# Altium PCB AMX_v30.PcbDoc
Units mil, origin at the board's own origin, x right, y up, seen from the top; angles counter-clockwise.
Board outline 2747.05 x 1800.98 mil, 4 copper layers (Top Layer, Internal Plane 1, Internal Plane 2, Bottom Layer), stack 30.634 mil thick; 78 components, 60 nets, 302 pads, 54 vias.
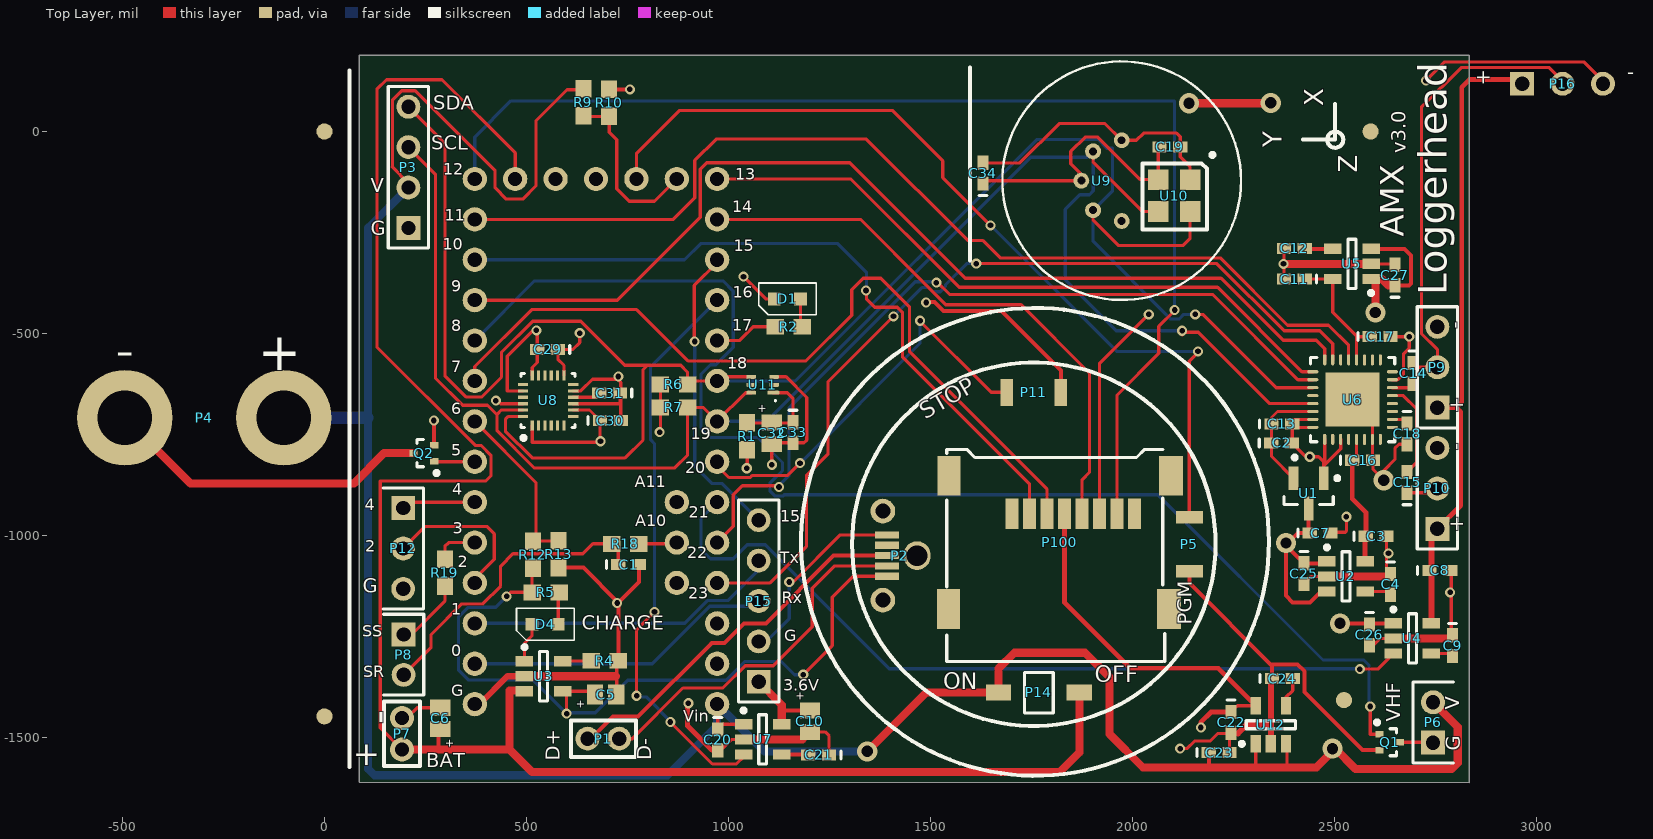
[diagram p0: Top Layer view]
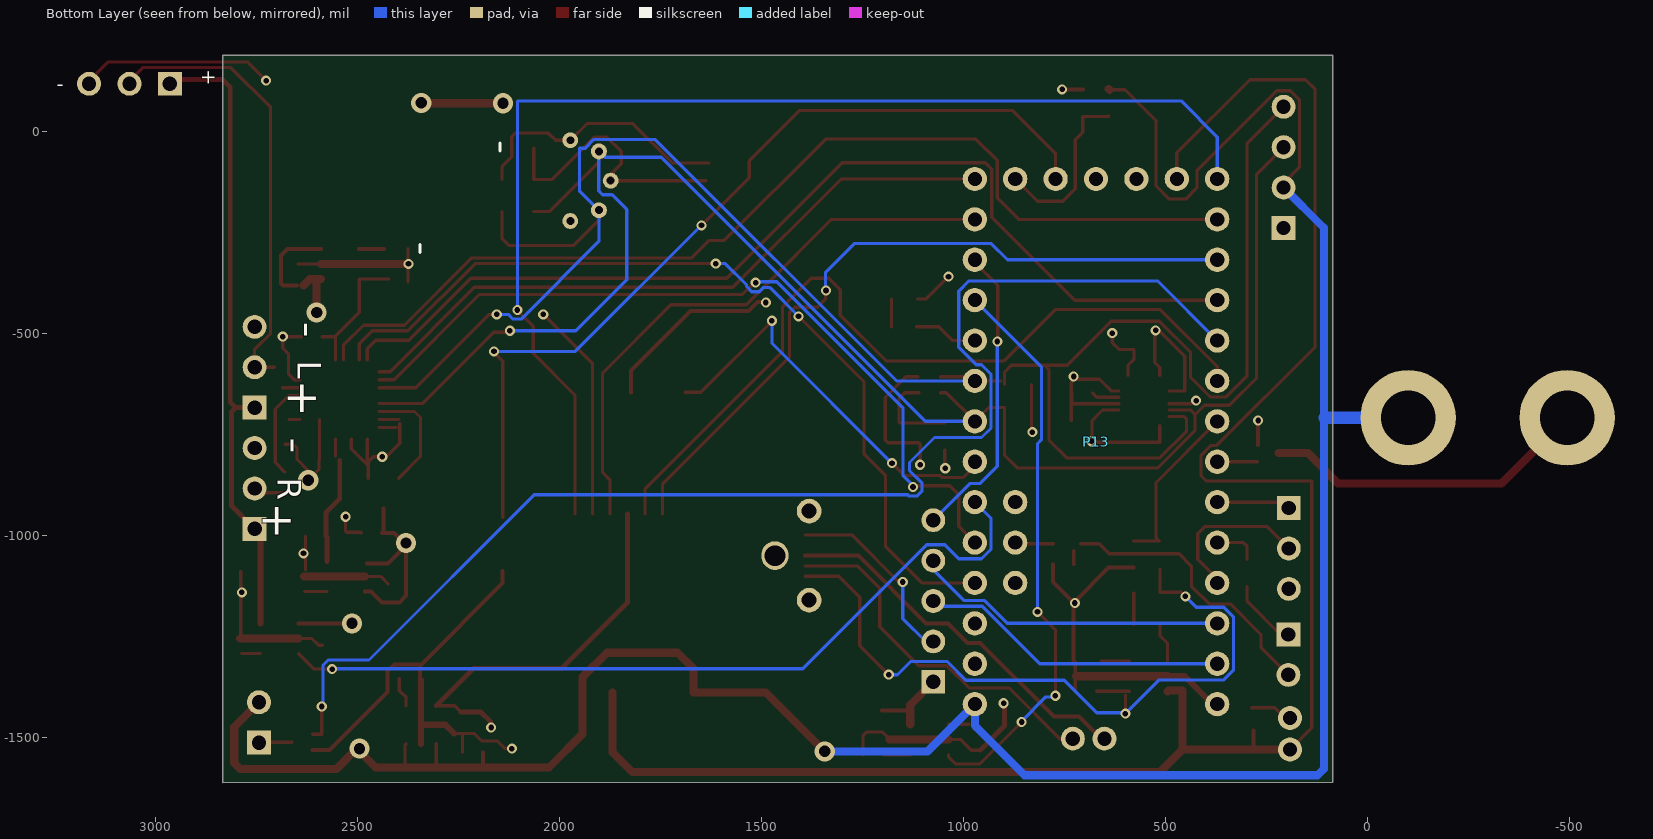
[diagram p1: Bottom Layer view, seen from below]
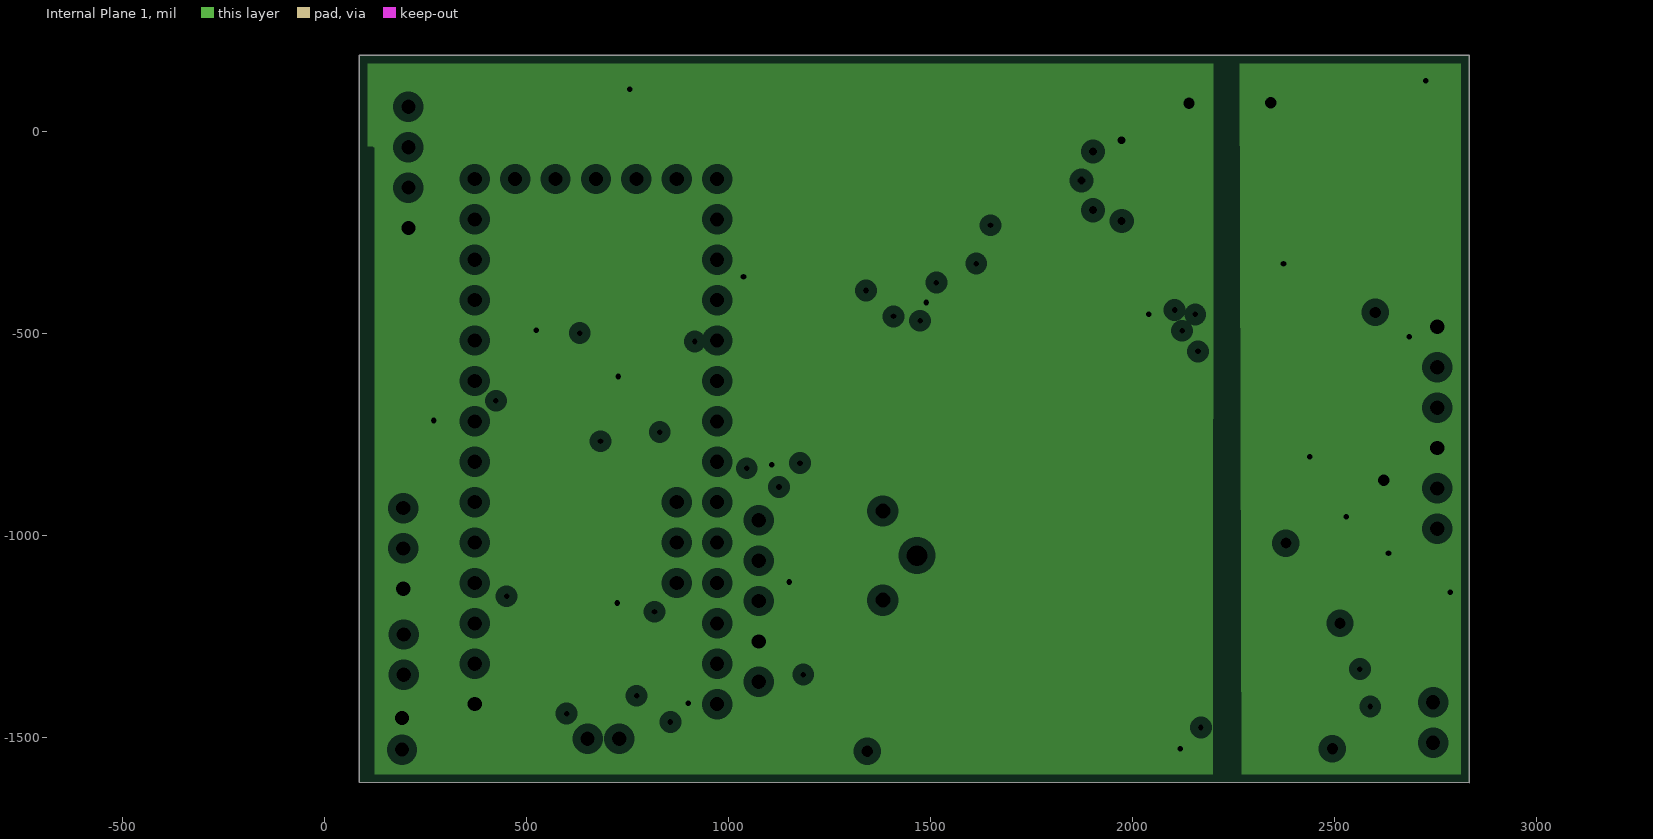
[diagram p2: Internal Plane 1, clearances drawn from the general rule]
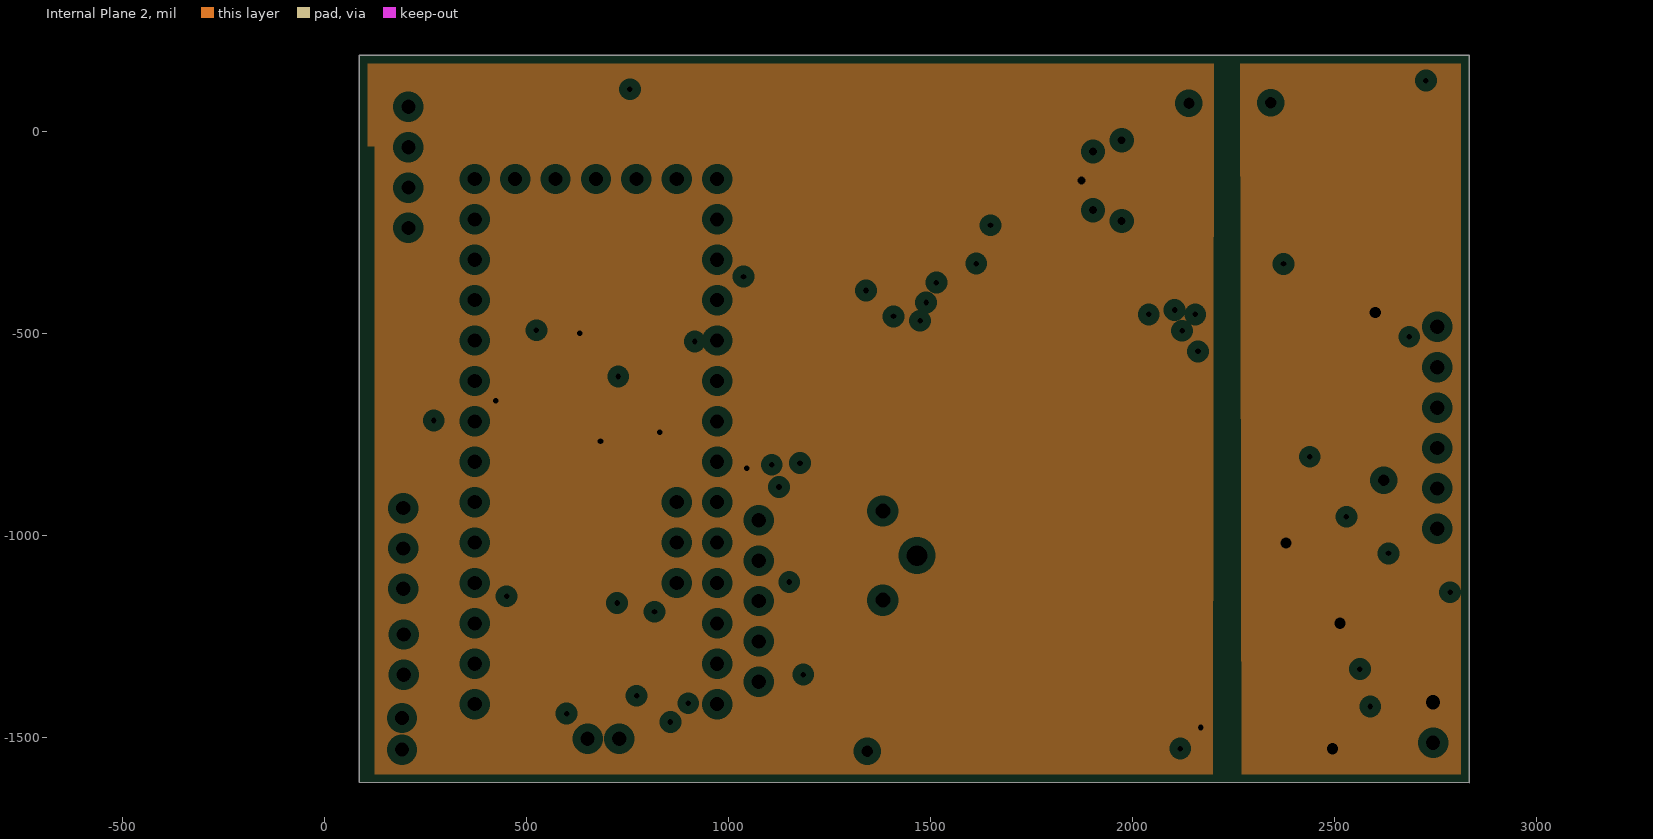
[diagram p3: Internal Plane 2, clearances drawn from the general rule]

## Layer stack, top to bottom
Top Solder: solder mask 0.4, Solder Resist, Dk 3.5
Top Layer: signal copper 1.4
Dielectric 1: core 10, FR-4, Dk 4.2
Internal Plane 1: plane copper 1.417, net DGND
Dielectric 3: prepreg 5, Dk 4.2
Internal Plane 2: plane copper 1.417, net (Multiple Nets)
Dielectric 2: core 10, Dk 4.2
Bottom Layer: signal copper 1.4
Bottom Solder: solder mask 0.4, Solder Resist, Dk 3.5

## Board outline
86.61,-1611.22 86.61,188.78 2833.66,188.78 2833.66,-1612.2

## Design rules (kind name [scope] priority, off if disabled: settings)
Clearance [All] p1: gap=6
HoleToHoleClearance [All] p1: gap=6 allowstackedmicrovias=TRUE
MinimumSolderMaskSliver [All] p1: minsoldermaskwidth=6
PlaneClearance [All] p1: clearance=20
PlaneConnect [All] p1: planeconnectstyle=Relief reliefexpansion=20 reliefentries=4 reliefconductorwidth=10 reliefairgap=10
PolygonConnect [All] p1: connectstyle=Relief reliefconductorwidth=10 reliefentries=4 polygonreliefangle="90 Angle" airgapwidth=10
RoutingVias [All] p1: holewidth=28 width=50 viastyle="Through Hole" minholewidth=10 minwidth=10 maxholewidth=100 maxwidth=200
SilkToSilkClearance [All] p1: silktosilkclearance=0
SilkToSolderMaskClearance [IsPad] p1: minsilkscreentomaskgap=2 clearancetoexposedcopper=TRUE
SolderMaskExpansion [All] p1: expansion=4
Width Width_1 [All] p1: maxlimit=50 minlimit=6 preferedwidth=8
Width [All] p2: maxlimit=100 minlimit=6 preferedwidth=10
23 further rules are at their usual default settings.

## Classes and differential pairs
component class AMX_audio30: C13 C14 C15 C16 C17 C18 P9 P10 P16 U6
component class AMX_sensors30: C1 C19 C29 C30 C31 C32 C33 C34 P4 P6 P8 P12 P15 Q1 Q2 R1 R6 R7 R18 R19 U8 U9 U10
component class AMX30: C2 C3 C4 C5 C6 C7 C8 C9 C10 C11 C12 C20 C21 C22 C23 C24 C25 C26 C27 D1 D4 P1 P2 P3 P5 P7 P11 P13 P14 P100 R2 R4 R5 R9 R10 R12 R13 U1 U2 U3 U4 U5 U7 U12

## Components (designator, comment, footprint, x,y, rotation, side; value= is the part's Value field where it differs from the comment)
C1 "1.0uF" 0402#1 752.95,-1071.85 r0 top
C2 "1.0uF" 0402#1 2369.09,-770.67 r0 top
C3 "1.0uF" 0402#1 2603.35,-1001.97 r0 top
C4 "10nF" 0402#1 2638.78,-1121.06 r270 top
C5 "1uF" Tant0805 695.87,-1393.7 r180 top
C6 "1uF" Tant0805 286.42,-1452.76 r270 top
C7 "1.0uF" 0402#1 2464.57,-994.09 r0 top
C8 "1.0uF" 0402#1 2760.83,-1086.61 r0 top
C9 "10nF" 0402#1 2792.32,-1272.64 r270 top
C10 "10uF" Tant0805 1201.77,-1459.65 r90 top
C11 "1.0uF" 0402#1 2400.59,-365.16 r180 top
C12 "10nF" 0402#2 2400.59,-289.37 r180 top
C13 "0.1uF" 0402#1 2369.85,-723.61 r0 top
C14 "1.0uF" 0402#1 2694.84,-598.62 r270 top
C15 "1.0uF" 0402#1 2679.84,-868.62 r90 top
C16 "0.1uF" 0402#1 2569.84,-813.62 r0 top
C17 "0.1uF" 0402#1 2613.19,-507.87 r0 top
C18 "0.1uF" 0402#1 2679.85,-748.61 r270 top
C19 "0.1uF" 0402#2 2092.52,-38.39 r0 top
C20 "1.0uF" 0402#1 973.43,-1505.91 r270 top
C21 "470pF" 0402#1 1223.43,-1543.31 r180 top
C22 "1.0uF" 0402#1 2244.09,-1462.6 r270 top
C23 "1.0uF" 0402#1 2214.57,-1537.4 r0 top
C24 "10nF" 0402#1 2371.06,-1354.33 r0 top
C25 "1.0uF" 0402#1 2424.21,-1094.49 r270 top
C26 "1.0uF" 0402#1 2586.61,-1246.06 r270 top
C27 "1.0uF" 0402#1 2649.61,-355.31 r90 top
C29 "0.1uF" 0402#1 552.17,-539.37 r180 top
C30 "10nF" 0402#1 707.68,-715.55 r0 top
C31 "0.1uF" 0402#1 705.71,-647.64 r180 top
C32 "1uF" Tant0805 1107.28,-747.05 r90 top
C33 "0.1uF" 0402#1 1159.45,-745.08 r270 top
C34 "0.1uF" 0402#1 1629.92,-103.35 r90 top
D1 "LED_0603" Diode0603 1145.67,-414.37 r180 top
D4 "LED_0603" Diode0603 546.26,-1219.49 r180 top
P1 "USB" HDR_2x1_2mm 650.59,-1502.95 r270 top
P2 "microUSB-vert" MICROUSB-VERT 1392.05,-1100.98 r90 top
P3 "Display" HDR1X4 207.8,-238.78 r90 top
P4 "Burn" BURN -100.39,-708.66 r180 top
P5 "Tactile" Tactile-B3U-1000 2140.75,-1021.65 r90 top
P6 "VHF Power" HDR1X2 2744.09,-1512.8 r90 top
P7 "Battery _2mm" HDR_2x1_2mm 191.93,-1530.51 r0 top
P8 "Salt Switch" HDR1X2 195.87,-1245.08 r270 top
P9 "HYDROPHONE" HDR1X3 2754.84,-683.62 r90 top
P10 "HYDROPHONE" HDR1X3 2754.84,-983.62 r90 top
P11 "Tactile" Tactile-B3U-1000 1755.91,-645.67 r180 top
P12 "Header 3" HDR1X3 194.88,-932.09 r270 top
P13 "Teensy3.x" Teensy3.x 372.05,-1217.52 r180 bottom
P14 "DIP1" DIP1 1868.43,-1388.38 r180 top
P15 "Header 5" HDR1X5 1074.8,-1362.2 r90 top (schematic designator P9)
P16 "HYDROPHONE" HDR1X3 2964.57,118.11 r0 top
P100 "microSD-Molex" microSD_Molex_hinged 2075.12,-851.97 r270 top
Q1 "DMN5L06TK-7" SOT-523 2636.81,-1511.81 r0 top
Q2 "DMN5L06TK-7" SOT-523 246.06,-796.26 r180 top
R1 "100x" 3-0603 1046.26,-754.92 r90 top
R2 "330" 3-0603 1149.61,-483.27 r0 top
R4 "2k" 3-0603 693.9,-1310.04 r180 top
R5 "330" 3-0603 547.24,-1140.75 r0 top
R6 "4.7k" 3-0603 865.16,-625.98 r0 top
R7 "4.7k" 3-0603 865.16,-683.07 r180 top
R9 "100k" 3-0603 640.75,71.85 r90 top
R10 "100k" 3-0603 704.72,70.87 r270 top
R12 "100k" 3-0603 515.75,-1047.24 r90 top
R13 "100k" 3-0603 579.72,-1046.26 r270 top
R18 "10k" 3-0603 744.09,-1020.67 r180 top
R19 "1k" 3-0603 298.23,-1092.52 r90 top
U1 "MCP1700T-1802E/TT" SOT-23-TT3_N 2436.02,-895.67 r270 top
U2 "LP3985IM5-3.3" MF05A_N 2528.54,-1101.38 r0 top
U3 "MCP73831T-2DCI/OT" SOT-23-OT5_N 542.32,-1348.43 r0 top
U4 "LP3985IM5-3.3" MF05A_N 2692.91,-1254.92 r0 top
U5 "LP3985IM5-3.3" MF05A_N 2543.31,-327.76 r180 top
U6 "SGTL5000" QFN32 2544.85,-663.61 r90 top
U7 "3.6V LDO" MF05A_N 1084.65,-1504.92 r0 top
U8 "MPU9250" MPU6500 553.57,-665.85 r90 top
U9 "Keller7LD" Keller7LD 1973.43,-21.65 r270 top
U10 "MS5837" MS5837 2142.72,-119.09 r270 top
U11 "RGB light" ODFN 1084.65,-626.97 r180 top
U12 "LP3985IM5-3.3" MF05A_N 2342.52,-1468.5 r90 top

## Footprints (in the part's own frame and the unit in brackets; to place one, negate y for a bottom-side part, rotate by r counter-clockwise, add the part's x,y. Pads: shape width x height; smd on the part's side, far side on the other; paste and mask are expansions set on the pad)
3-0603 [mm] "Chip Resistor; Body 1.6 x 0.9 mm (LxW typ)"
  rect 1.1x1 smd: 1(-0.85,0) 2(0.85,0)
0402#1 [mm] "Chip Capacitor; Body 1.0 x 0.5 mm (LxW typ)"
  rect 0.9x0.7 smd: 1(-0.65,0) 2(0.65,0)
  silkscreen extent -1.4,-0.25 -1.4,0.25
0402#2 [mm] "Chip Capacitor; Body 1.0 x 0.5 mm (LxW typ)"
  rect 0.9x0.7 smd: 1(0.65,0) 2(-0.65,0)
BURN [mm]
  round 6 hole 3.42: 1(0,0) 2(10,0)
Diode0603 [mm]
  rect 0.8x0.8 smd: A(-0.825,0) K(0.825,0)
  silkscreen extent -1.83,-1 1.8,1
DIP1 [mm]
  rect 1.6x1 smd: 1(0,0) 2(5.08,0)
  silkscreen extent 1.63,-1.25 3.45,1.29
HDR1X2 [mm] "Connector; Header; 2 Position"
  rect 1.5x1.5 hole 0.9: 1(0,0)
  round 1.5 hole 0.9: 2(2.54,0)
  silkscreen extent -1.27,-1.27 3.81,1.27
HDR1X3 [mm] "Connector; Header; 3 Position"
  rect 1.5x1.5 hole 0.9: 1(0,0)
  round 1.5 hole 0.9: 2(2.54,0) 3(5.08,0)
  silkscreen extent -1.27,-1.27 6.35,1.27
HDR1X4 [mm] "Connector; Header; 4 Position"
  rect 1.5x1.5 hole 0.9: 1(0,0)
  round 1.5 hole 0.9: 2(2.54,0) 3(5.08,0) 4(7.62,0)
  silkscreen extent -1.27,-1.27 8.89,1.27
HDR1X5 [mm] "Connector; Header; 5 Position"
  rect 1.5x1.5 hole 0.9: 1(0,0)
  round 1.5 hole 0.9: 2(2.54,0) 3(5.08,0) 4(7.62,0) 5(10.16,0)
  silkscreen extent -1.27,-1.27 11.43,1.27
HDR_2x1_2mm [mm]
  round 1.5 hole 0.9: 1(0,0.016) 2(0,2)
  silkscreen extent -1.14,-1.02 1.14,3.05
Keller7LD [mm]
  round 1 hole 0.5: 1(5.08,0) 2(4.4,-1.8) 3(2.54,-2.54) 4(0.7,-1.8) 5(0,0)
  silkscreen extent -4.96,-7.5 10.04,7.5, body extent -4.94,-7.49 10,7.49, height 5.25
MF05A_N [mm] "SOT23, 5-Leads, Body 2.9x1.6mm, Pitch 0.95mm, Lead Span 2.8mm, IPC Medium Density"
  rect 1.1x0.65 smd: 1(-1.2,0.95) 2(-1.2,0) 3(-1.2,-0.95) 4(1.2,-0.95) 5(1.2,0.95)
  silkscreen extent -1.32,-1.55 0.25,1.95, body extent -0.9,-1.55 0.9,1.55, height 1.19
microSD_Molex_hinged [mm]
  rect 2.5x1.5 smd: 0(0,0.508) 0(8.382,0.381)
  rect 2.5x1.45 smd: 0(0,-13.45) 0(8.382,-13.462)
  rect 1.9x0.8 smd: 1(2.4,-9.475) 2(2.4,-8.375) 3(2.4,-7.275) 4(2.4,-6.175) 5(2.4,-5.075) 6(2.4,-3.975) 7(2.4,-2.875) 8(2.4,-1.775)
  silkscreen extent -1.65,-13.59 11.68,0.13
MICROUSB-VERT [mm] "Molex 05133-0011"
  rect 0.45x1.5 smd: 1(0,0) 2(0.65,0) 3(1.3,0) 4(1.95,0) 5(2.6,0)
  round 1.55 hole 0.95: ""(-1.5,0.25) ""(4.1,0.25)
  oval 1.8x1.7 hole 1.3: ""(1.3,-1.9)
  body extent -2.67,-3.05 5.35,1.4, height 7.53
MPU6500 [mm] "QFN, 24-Leads, Body 3.00x3.00mm, Pitch 0.40mm, Thermal Pad 1.54x1.54mm, IPC Medium Density"
  rect 0.65x0.2 smd: 1(-1.575,1) 2(-1.575,0.6) 3(-1.575,0.2) 4(-1.575,-0.2) 5(-1.575,-0.6) 6(-1.575,-1) 13(1.575,-1) 14(1.575,-0.6) 15(1.575,-0.2) 16(1.575,0.2) 17(1.575,0.6) 18(1.575,1)
  rect 0.2x0.65 smd: 7(-1,-1.575) 8(-0.6,-1.575) 9(-0.2,-1.575) 10(0.2,-1.575) 11(0.6,-1.575) 12(1,-1.575) 19(1,1.575) 20(0.6,1.575) 21(0.2,1.575) 22(-0.2,1.575) 23(-0.6,1.575) 24(-1,1.575)
  silkscreen extent -2.47,-1.7 1.7,1.7, body extent -1.85,-1.25 1.25,1.85, height 0.9
MS5837 [mm]
  rect 1.3x1.3 smd: 1(0,0) 2(0,-2) 3(2,-2) 4(2,0)
  silkscreen extent -1.67,-3 3.15,1.52
ODFN [mm]
  rrect50% 0.75x0.25 smd: 1(-0.67,0.5)
  rrect50% 0.6x0.25 smd: 2(-0.72,0) 3(-0.72,-0.5) 4(0.72,-0.5) 5(0.72,0) 6(0.72,0.5)
  silkscreen extent -0.85,0.95 -0.75,1.05, body extent -0.82,-0.82 0.82,0.82, height 0.7
QFN32 [mm]
  oval 0.7x0.2 smd: 1(-2.5,1.75) 2(-2.5,1.25) 3(-2.5,0.75) 4(-2.5,0.25) 5(-2.5,-0.25) 6(-2.5,-0.75) 7(-2.5,-1.25) 8(-2.5,-1.75) 17(2.5,-1.75) 18(2.5,-1.25) 19(2.5,-0.75) 20(2.5,-0.25) 21(2.5,0.25) 22(2.5,0.75) 23(2.5,1.25) 24(2.5,1.75)
  oval 0.2x0.7 smd: 9(-1.75,-2.5) 10(-1.25,-2.5) 11(-0.75,-2.5) 12(-0.25,-2.5) 13(0.25,-2.5) 14(0.75,-2.5) 15(1.25,-2.5) 16(1.75,-2.5) 25(1.75,2.5) 26(1.25,2.5) 27(0.75,2.5) 28(0.25,2.5) 29(-0.25,2.5) 30(-0.75,2.5) 31(-1.25,2.5) 32(-1.75,2.5)
  rect 3.4x3.4 smd paste-1.2: 33(0,0)
  silkscreen extent -3.77,-2.65 2.65,3.76, body extent -2.5,-2.5 2.5,2.5, height 1
SOT-23-OT5_N [mm] "SOT23, 5-Leads, Body 2.9x1.7mm, Pitch 0.95mm, Lead Span 2.8mm, IPC Medium Density"
  rect 1.1x0.65 smd: 1(-1.2,0.95) 2(-1.2,0) 3(-1.2,-0.95) 4(1.2,-0.95) 5(1.2,0.95)
  silkscreen extent -1.32,-1.55 0.25,1.95, body extent -0.9,-1.55 0.9,1.55, height 1.45
SOT-23-TT3_N [mm] "SOT23, 3-Leads, Body 2.9x1.3mm, Pitch 0.95mm, Lead Span 2.4mm, IPC Medium Density"
  rect 1.5x0.6 smd: 1(-0.95,0.95) 2(-0.95,-0.95) 3(0.95,0)
  silkscreen extent -1.07,-1.55 0.7,1.93, body extent -0.7,-1.52 0.7,1.53, height 1.12
SOT-523 [mm] "For Diodes Inc MOSFET DMN5L06TK"
  rect 0.51x0.4 smd: 1(-0.65,0.5) 2(-0.65,-0.5) 3(0.65,0)
  silkscreen extent -0.92,-0.85 0.42,1.37, body extent -0.43,-0.85 0.42,0.85, height 0.8
Tactile-B3U-1000 [mm]
  rect 0.8x1.7 smd: 1(-1.7,0) 2(1.7,0)
Tant0805 [mil]
  rect 40x50 smd: 1(-26.5,0) 2(26.5,0)
Teensy3.x [mil]
  round 60 hole 35: 0(0,-100) 1(0,0) 2(0,100) 3(0,200) 3.3V(-600,0) 3.3V2(-200,1100) 4(0,300) 5(0,400) 6(0,500) 7(0,600) 8(0,700) 9(0,800) 10(0,900) 11(0,1000) 12(0,1100) 13(-600,1100) 14(-600,1000) 15(-600,900) 16(-600,800) 17(-600,700) 18(-600,600) 19(-600,500) 20(-600,400) 21(-600,300) 22(-600,200) 23(-600,100) A10(-500,200) A11(-500,300) A14(-500,1100) AGND(-600,-100) AREF(-500,100) GND(0,-200) GND2(-300,1100) PGM(-400,1100) VBat(-100,1100) Vin(-600,-200)

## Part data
C1 C2 C3 C4 C7 C8 C9 C11 C12 C13 C14 C15 C16 C17 C18 C19 C20 C21 C22 C23 C24 C25 C26 C27 C29 C30 C31 C33 C34: library part C0402, "Ceramic Chip Capacitor - Standard"
C5 C6 C10 C32: library part Tant0805
P1 P7: library part HDR_2x1_2mm, "Charging Connector"
P2: "Molex 105133-0011"
P3: library part "Header 4", "Header, 4-Pin"
P4: library part "Burn Screw"
P5 P11: library part Tactile_B3U-1000
P6 P8: library part "Header 2", "Header, 2-Pin"
P9 P10 P16: library part "Header 3", "Header, 3-Pin"
P12: "Header, 3-Pin"
P15: "Header, 5-Pin"
P100: library part microSD_Molex_hinged
Q1 Q2: library part "FET DMN5L06TK-7", "Ultra-low leakage Enhanced MOSFET"
R1 R2 R4 R5 R6 R7 R9 R10 R12 R13 R18 R19: library part ERJ3RK, "Precision Thick Film Chip Resistor, 10 Ohm to 1M Ohm Range, 1% and 0.5% Tolerance, 0603 Size, 0.063 W"
U1: "Low Quiescent Current LDO, 3-Pin SOT-23, Extended Temperature, Tape and Reel"
U2 U4 U5 U12: "Micropower, 150mA Low-Noise Ultra Low-Dropout CMOS Voltage Regulator"
U3: "Miniature Single-Cell, Fully Integrated Li-Ion, Li-Polymer Charge Management Controller, 4.2V, 5-Pin SOT-23, Industrial Temperature, Tape and Reel"
U7: library part LP3985IM5-3.3, "Micropower, 150mA Low-Noise Ultra Low-Dropout CMOS Voltage Regulator"
U8: library part MPU-9250, "Invensense"
U9: library part "Keller 7LD", "Keller Pressure/Temp"
U10: "Pressure/Temp"
U11: library part ISL29125, "RGB light sensor"

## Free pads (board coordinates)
  round 40 smd paste-20 mask+5: 0(0,-1447.83) 0(0,0) 0(2523.62,-1407.48) 0(2589.57,0)

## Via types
v1: diameter 25, hole 14, Top Layer to Bottom Layer, 46 vias
v2: diameter 50, hole 28, Top Layer to Bottom Layer, 8 vias

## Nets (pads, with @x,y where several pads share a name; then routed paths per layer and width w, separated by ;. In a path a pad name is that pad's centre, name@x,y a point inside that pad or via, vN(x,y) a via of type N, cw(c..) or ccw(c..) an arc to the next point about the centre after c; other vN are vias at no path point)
AGND: C2.2 C3.2 C4.1 C7.2 C8.2 C9.1 C11.2 C12.1 C13.2 C16.2 C17.2 C18.2 C25.2 C26.2 C27.2 P9.3 P10.3 P16.3 U1.1 U2.2 U4.2 U5.2 U6.1 U6.3 U6.7 U6.15 U6.31 U6.32 U6.33 | length 2451.6
  Top Layer w8: C11.2@2375,-372.05 C11.2 2375,-318.9 C12.1 ; C2.2 2429.13,-805.12 v1(2438.98,-805.12) 2460.63,-805.12 2473.43,-817.91 U1.1 ; C2.2@2395.44,-769.91 C13.2 ; C13.2@2397.86,-712.82 U6.31 ; C13.2@2404.34,-732.51 U6.32 ; C25.2 2442.91,-1101.38 U2.2 ; U6.1 2475.96,-824.8 2515.33,-785.43 U6.3 ; C7.2 2492.13,-992.13 2526.57,-992.13 2529.53,-989.17 v1(2529.53,-953.74) ; C26.2 2596.46,-1271.65 2613.19,-1254.92 U4.2 ; U5.2 C27.2@2647.64,-327.76 ; C16.2@2594.07,-812.26 U6.7 U6.33@2594.07,-712.82 ; C16.2 2595.43,-836.57 v2(2622.05,-863.19) 2622.05,-839.57 2649.61,-812.01 2649.61,-784.45 2659.86,-774.2 C18.2 ; C4.1@2628.94,-1085.63 C3.2 ; C17.2 v1(2685.04,-507.87) 2685.04,-536.01 2671.06,-549.99 2671.06,-599.61 2656.27,-614.4 U6.15 ; v1(2726.38,125.98) 2772.64,172.24 3117.32,172.24 P16.3@3160.63,128.94 ; C9.1@2789.37,-1248.03 C8.2@2789.37,-1089.57
  Top Layer w20: v1@2375.98,-327.76 U5.2 ; U2.2 C4.1@2632.87,-1101.38 ; U4.2 C9.1@2790.35,-1254.92
  other v1: 2786.42,-1140.75 2633.86,-1044.29 2374.02,-327.76
  other v2: 2342.52,70.87
BCLK: P13.9 U6.24 | length 2532.4
  Top Layer w8: P13.9 725.2,-417.52 930.34,-212.38 930.34,-93.28 946.1,-77.52 1299.96,-77.52 1585.63,-363.19 2219.49,-363.19 2373.03,-516.73 2454.72,-516.73 2475.96,-537.96 U6.24
BURN: P13.5 Q2.1 | length 98.8
  Top Layer w8: Q2.1@273.23,-817.52 P13.5
BURN_GND: P4.2 Q2.3 | length 812.8
  Top Layer w20: P4.2 -331.69,-871.06 72.83,-871.06 147.64,-796.26 Q2.3
CAM_SW: P12.1 P13.4 | length 183.2
  Top Layer w8: P12.1 209.45,-917.52 P13.4
CS: P13.10 P100.2 | length 1813.2
  Top Layer w8: v1@1341.54,-394.69 1341.54,-414.37 1362.34,-435.18 1417.78,-435.18 1430.96,-448.36 1430.96,-558.92 1745.4,-873.35 P100.2
  Bottom Layer w8: P13.10 891.14,-317.52 931.14,-277.52 1270.63,-277.52 1341.54,-348.43 v1@1341.54,-394.69
  other v1: 1340.55,-393.7
D2: P12.2 P13.2 | length 397.1
  Top Layer w8: P12.2 249.45,-977.52 401.73,-977.52 420.28,-996.06 420.28,-1059.06 372.05,-1107.28 P13.2
D15: P13.15 P15.5 | length 749.4
  Top Layer w8: v1@915.35,-520.67 915.35,-380.91 972.05,-324.21 P13.15
  Bottom Layer w8: v1(916.34,-519.69) 916.34,-828.74 958.66,-871.06 983.66,-871.06 P15.5
D+: P1.1 P2.3 | length 937
  Top Layer w10: P1.1@659.45,-1502.95 714.57,-1447.83 776.57,-1447.83 958.66,-1265.75 990.2,-1265.75 1038.43,-1217.52 1092.52,-1217.52 1260.24,-1049.8 P2.3
  Top Layer w20: P1.1@651.22,-1494.45 P1.1 P1.1@659.45,-1502.95
D-: P1.2 P2.2 | length 895.7
  Top Layer w8: P1.2 761.81,-1502.95 887.24,-1377.52 986.29,-1377.52 1041.13,-1322.68 1111.38,-1322.68 1207.68,-1226.38 1207.68,-1130.91 1263.19,-1075.39 P2.2
DGND: C1.2 C5.1 C6.1 C10.1 C19.1 C20.2 C21.1 C22.2 C23.2 C24.1 C29.2 C30.2 C31.1 C32.1 C33.2 C34.2 D1.K P2.5 P3.1 P5.1 P7.2 P11.1 P12.3 P13.GND P15.2 P100.6 Q1.2 Q2.2 R4.1 R10.1 R13.2 U3.2 U7.2 U8.9 U8.11 U8.18 U8.20 U9.5 U10.1 U11.3 U12.2 | length 6143.7
  Top Layer w8: P7.2 203.74,-1451.77 229.26,-1426.26 C6.1 ; P13.GND P13.GND@383.66,-1417.52 ; U8.20 452.27,-642.23 452.27,-556.59 514.76,-494.09 526.57,-494.09 C29.2 526.57,-571.85 514.2,-584.23 U8.18 ; U8.9 728.83,-673.72 731.3,-671.26 C31.1 ; U8.11 634.35,-642.23 663.39,-613.19 725.39,-613.19 733.27,-621.06 C30.2 ; C5.1@723.35,-1385.83 R4.1@723.35,-1314.05 ; v1@898.62,-1421.26 v1@904.53,-1415.35 ; 958.66,-1531.5 C20.2 981.3,-1531.5 1007.87,-1504.92 U7.2 ; v1(1037.4,-359.25) 1092.52,-414.37 D1.K ; v1(1107.28,-824.8) C32.1 ; C32.1@1110.16,-770.67 C33.2 1187.01,-770.67 1193.9,-763.78 1193.9,-658.46 1142.72,-607.28 U11.3 ; v1@1150.59,-1117.13 1158.46,-1117.13 1276.97,-998.62 P2.5 ; C10.1@1183,-1504.92 C10.1 1239.1,-1486.15 1249.02,-1496.06 C21.1 ; C34.2 1721.46,-77.76 1818.9,19.69 1932.09,19.69 U9.5 2009.84,-21.65 2027.56,-3.94 2109.25,-3.94 2118.11,-12.8 C19.1 2118.11,-62.99 2142.72,-87.6 U10.1 ; P100.6 1918.63,-573.5 v1@2042.32,-449.8 ; v1(2118.11,-1527.56) 2134.84,-1527.56 2153.54,-1508.86 2191.93,-1508.86 2210.63,-1490.16 2260.83,-1490.16 ; C23.2 C22.2@2240.16,-1492.13
  Top Layer w10: Q2.2 v1@271.65,-716.54 ; R13.2 640.75,-1079.72 v1@726.38,-1165.35 ; R10.1 v1(755.91,104.33) ; R4.1 727.36,-1166.34 778.54,-1115.16 C1.2 ; v1@1490.16,-422.24 1509.96,-422.24 1531.85,-444.13 1675.43,-444.13 1822.83,-591.54 P11.1 ; P5.1 2140.75,-1118.11 2345.47,-1322.83 C24.1 2345.47,-1318.9 2408.27,-1318.9 2425.37,-1335.99 2425.37,-1386.98 2569.88,-1531.5 Q1.2
  Top Layer w12: v1@898.62,-1421.26 898.62,-1471.46 958.66,-1531.5
  Top Layer w15: P13.GND@383.66,-1417.52 452.76,-1348.43 U3.2 ; 2260.83,-1490.16 2282.48,-1468.5 2342.52,-1468.5 ; U12.2 2342.52,-1468.5 ; C24.1@2342.52,-1357.28 2342.52,-1468.5
  Top Layer w20: U3.2 721.38,-1348.43 ; U7.2 C10.1@1183,-1504.92
  Bottom Layer w8: P15.2 1094.09,-1262.2 1150.59,-1205.71 v1(1150.59,-1115.16)
  other v1: 900.59,-1415.35 724.41,-1167.32 270.67,-715.55 727.36,-606.3 524.61,-492.13 2040.35,-452.76 1489.17,-423.23
  other v2: 2139.76,69.88
HL: C14.1 P9.2 P16.2 | length 1107.3
  Top Layer w8: C14.1@2705.43,-583.62 P9.2 2754.84,-539.52 2715.31,-499.99 2715.31,59.8 2813.58,158.07 3031.5,158.07 P16.2@3060.63,128.94
HYDRO_EN: P13.21 U4.3 | length 2015
  Top Layer w8: v1(2562.99,-1330.71) 2607.28,-1330.71 U4.3
  Bottom Layer w8: P13.21 932.05,-957.52 932.05,-1034.09 955.48,-1057.52 1011.84,-1057.52 1046.69,-1022.68 1091.18,-1022.68 1398.22,-1329.72 v1@2563.98,-1329.72
I2SDIN: P13.22 U6.26 | length 2009.8
  Top Layer w8: P13.22 1012.05,-977.52 1012.05,-899.37 1034.45,-876.97 v1@1125,-876.97 ; v1@1516.73,-373.03 1547.24,-403.54 2198.82,-403.54 2409.67,-614.4 U6.26 U6.26@2445.67,-615.16
  Bottom Layer w8: P13.22 P13.22@972.05,-992.52 ; v1@1125,-876.97 1149.61,-852.36 1149.61,-684.72 1462.27,-372.05 v1@1514.76,-372.05
  other v1: 1125,-879.92 1514.76,-374.02
I2SDOUT: P13.13 U6.25 | length 1672
  Top Layer w8: P13.13 1302.56,-117.52 1570.87,-385.83 2210.63,-385.83 2419.51,-594.71 U6.25
IN_L: C14.2 U6.14 | length 41.7
  Top Layer w8: U6.14 C14.2@2684.97,-634.08
IN_R: C15.2 U6.13 | length 240.1
  Top Layer w8: U6.13 2670.5,-653.77 2703.63,-686.9 2703.63,-819.24 C15.2
LED1: P13.17 R2.1 | length 158.3
  Top Layer w8: P13.17 1026.77,-517.52 1061.02,-483.27 R2.1
LINE_IN_R: C15.1 P10.2 | length 79.4
  Top Layer w8: C15.1 2744.25,-894.21 P10.2
LRCLK: P13.23 U6.23 | length 2191.9
  Top Layer w8: P13.23 1102.95,-1117.52 1192.91,-1027.56 1192.91,-852.36 1246.06,-799.21 1246.06,-620.08 v1(1408.46,-457.68) ; v1(1613.41,-326.99) 2208.88,-326.99 2375.22,-493.33 2463.8,-493.33 2495.64,-525.17 U6.23
  Bottom Layer w8: v1(1408.46,-457.68) 1480.09,-386.05 1494.98,-386.05 1505.44,-396.52 1524.08,-396.52 1537.26,-383.34 1537.26,-379.07 1589.35,-326.99 v1(1613.41,-326.99)
MCLK: P13.11 U6.21 | length 2547.1
  Top Layer w8: P13.11 863.19,-217.52 916.34,-164.37 916.34,-71.72 969.36,-18.7 1341.54,-18.7 1592.52,-269.69 1628.94,-269.69 1672.24,-312.99 2217.52,-312.99 2383.86,-479.33 2485.24,-479.33 2535.01,-529.11 U6.21
MISO: P13.12 P100.7 | length 2954.4
  Top Layer w8: P100.7 1961.93,-652.24 2065.13,-549.04 2065.13,-482.46 v1@2105.31,-442.27
  Bottom Layer w8: P13.12 372.05,-13.78 461.61,75.79 2104.33,75.79 v1(2104.33,-441.93)
MOSI: P13.7 P100.3 | length 2027.2
  Top Layer w8: P13.7 372.05,-581.69 512.8,-440.94 772.64,-440.94 899.61,-567.91 1191.93,-567.91 1305.12,-454.72 1305.12,-391.73 1333.66,-363.19 1376.97,-363.19 1447.83,-434.06 1447.83,-544.29 1788.39,-884.84 1788.39,-946.13 P100.3
NetC1_1: C1.1 P8.2 R18.2 | length 731.2
  Top Layer w8: P8.2 263.78,-1277.17 263.78,-1245.08 339.57,-1169.29 391.73,-1169.29 435.84,-1125.18 435.84,-1075.97 466.38,-1045.43 639.61,-1045.43 664.37,-1020.67 R18.2 ; C1.1 R18.2@727.36,-1037.4
NetC4_2: C4.2 U2.4 | length 55.1
  Top Layer w8: U2.4 C4.2@2630.91,-1138.78
NetC9_2: C9.2 U4.4 | length 46.3
  Top Layer w8: U4.4 C9.2@2786.42,-1292.32
NetC12_2: C12.2 U5.4 | length 62
  Top Layer w10: C12.2@2434.06,-290.35 U5.4
NetC18_1: C18.1 U6.10 | length 26.4
  Top Layer w8: U6.10 C18.1@2669.66,-712.82
NetC21_2: C21.2 U7.4 | length 65
  Top Layer w10: U7.4 C21.2@1196.85,-1542.32
NetC24_2: C24.2 U12.4 | length 73.9
  Top Layer w8: U12.4 2379.92,-1400.59 2396.65,-1383.86 C24.2
NetC31_2: C31.2 U8.10 | length 68.8
  Top Layer w8: U8.10 669.78,-657.98 C31.2
NetC32_2: C32.2 C33.1 R1.2 U11.1 | length 224.4
  Top Layer w8: R1.2 C33.1@1157.48,-721.46 ; U11.1 1145.67,-646.65 1159.45,-660.43 C33.1
NetD1_A: D1.A R2.2 | length 68.9
  Top Layer w8: R2.2@1178.15,-483.27 D1.A
NetD4_A: D4.A R5.2 | length 76.8
  Top Layer w8: D4.A R5.2@578.74,-1142.72
NetD4_K: D4.K U3.1 | length 99.3
  Top Layer w8: U3.1 495.08,-1266.73 513.78,-1248.03 D4.K
NetP8_1: P8.1 R19.1 | length 173
  Top Layer w8: P8.1 215.55,-1245.08 298.23,-1162.4 R19.1
NetP13_6: P13.6 R12.2 R13.1 | length 425.3
  Top Layer w8: P13.6 523.62,-869.09 523.62,-1005.91 R12.2 R13.1@578.74,-1013.78
NetR4_2: R4.2 U3.5 | length 69.9
  Top Layer w8: U3.5 R4.2@659.45,-1311.02
PGM: P5.2 P13.PGM | length 2179.6
  Top Layer w8: P13.PGM 772.05,-54.72 878.94,52.17 1405.51,52.17 1530.51,-72.83 1530.51,-114.17 v1@1646.65,-230.31 ; P5.2 2140.75,-568.9 v1@2160.43,-549.21
  Bottom Layer w8: v1(1648.62,-232.28) 1960.63,-544.29 v1(2162.4,-544.29)
POW_EN: P13.16 U7.3 | length 1408
  Top Layer w8: v1(772.64,-1396.65) 772.64,-1233.27 v1(816.93,-1188.98) ; v1(856.3,-1461.61) 960.31,-1565.63 1019.69,-1565.63 1037.4,-1547.91 U7.3
  Bottom Layer w8: v1@777.56,-1399.61 796.26,-1399.61 v1@857.28,-1460.63 ; v1@816.93,-1185.04 816.93,-772.82 807.22,-763.12 807.22,-582.34 P13.16
RX: P13.0 P15.3 | length 767.1
  Bottom Layer w8: P13.0 811.42,-1317.52 953.74,-1175.2 1061.81,-1175.2 P15.3
SALT_READ: P13.A10 R18.1 | length 91.3
  Top Layer w8: R18.1 P13.A10@868.9,-1020.67
SALT_SIG: P13.3 R19.2 | length 110
  Top Layer w8: R19.2 298.23,-1026.57 307.28,-1017.52 P13.3
SCK: P13.14 P100.5 | length 1435.3
  Top Layer w8: P13.14 1326.77,-217.52 1492.26,-383.01 1492.26,-383.34 1538.06,-429.13 1724.41,-429.13 1893.7,-598.43 1893.7,-843.5 1875.32,-861.88 P100.5
SCL: P3.3 P13.19 R7.1 U6.29 U8.23 U9.4 U10.3 U11.6 | length 4287.7
  Top Layer w8: P3.3 274.61,-105.58 274.61,-610.24 341.89,-677.52 403.57,-677.52 425.86,-699.8 427.17,-699.8 ; U8.23 437.5,-689.47 427.17,-699.8 ; U11.6 1042.32,-646.65 971.46,-717.52 937.01,-683.07 R7.1 898.62,-801.18 867.13,-832.68 518.7,-832.68 427.17,-741.14 427.17,-699.8 ; U9.4 1902.56,-75.79 2024.61,-197.83 U10.3 ; v1@2123.03,-502.95 2128.94,-497.05 2163.39,-497.05 2339.79,-673.45 U6.29
  Bottom Layer w8: P13.19 1094.49,-717.52 1748.03,-63.98 1887.8,-63.98 U9.4 1903.11,-49.76 1903.11,-147.09 1893.7,-156.5 1870.08,-156.5 1833.66,-192.91 1833.66,-367.13 1959.65,-493.11 v1(2123.03,-493.11)
SDA: P3.4 P13.18 R6.2 U6.27 U8.24 U9.2 U10.4 U11.4 | length 4881.9
  Top Layer w8: P3.4 298.23,-29.21 298.23,-604.33 351.42,-657.52 388.62,-657.52 438.27,-607.87 438.27,-546.64 515.29,-469.63 634.32,-469.63 743.43,-578.74 799.21,-578.74 ; U8.24 455.21,-705.22 447.83,-712.6 447.83,-742.01 513.89,-808.07 744.09,-808.07 788.39,-763.78 788.39,-589.57 799.21,-578.74 ; R6.2 898.62,-595.47 881.89,-578.74 799.21,-578.74 ; R6.2@907.09,-617.52 P13.18 982.28,-607.28 U11.4 ; U9.2 1902.56,-219.49 1965.55,-282.48 2125,-282.48 2142.72,-264.76 U10.4 ; v1(2155.51,-452.76) 2174.21,-452.76 2355.54,-634.08 U6.27
  Bottom Layer w8: P13.18 1165.94,-617.52 1763.94,-19.53 1914.86,-19.53 1936.67,-41.34 1950.79,-41.34 1950.79,-146.65 U9.2 1902.56,-271.98 2095.01,-464.43 2115.16,-464.43 2126.83,-452.76 v1(2155.51,-452.76)
STOP: P11.2 P13.20 | length 1000.7
  Top Layer w8: P13.20 972.05,-827.36 1001.2,-856.52 1054.24,-856.52 1059.38,-851.38 1146.65,-851.38 v1@1175.2,-822.83 ; v1@1475.39,-470.47 1650.59,-645.67 P11.2
  Bottom Layer w8: v1(1177.17,-820.87) 1474.41,-523.62 v1(1474.41,-468.5)
TX: P13.1 P15.4 | length 780.2
  Bottom Layer w8: P13.1 891.62,-1217.52 947.94,-1161.2 998.25,-1161.2 1074.8,-1084.65 P15.4
USBSENSE: C5.2 P2.1 R5.1 R12.1 U3.4 | length 1867.4
  Top Layer w8: v1(450.79,-1150.59) 460.63,-1140.75 R5.1 R12.1@513.78,-1082.68 ; U3.4 C5.2@670.35,-1385.83 ; v1(599.41,-1440.94) U3.4@599.41,-1395.67 ; v1(1185.04,-1344.49) 1256.89,-1272.64 1256.89,-1152.56 1308.47,-1100.98 P2.1
  Bottom Layer w8: v1(450.79,-1150.59) 423.86,-1177.52 355.48,-1177.52 332.05,-1200.95 332.05,-1334.09 355.48,-1357.52 515.98,-1357.52 v1@597.44,-1438.98 ; v1(599.41,-1440.94) v1@597.44,-1438.98 ; v1(1185.04,-1344.49) 1163.39,-1344.49 1130.91,-1312.01 1040.35,-1312.01 994.09,-1358.27 750.98,-1358.27 670.28,-1438.98 v1@597.44,-1438.98
V3.6: C10.2 P15.1 U7.5 | length 196.9
  Top Layer w10: 1133.78,-1433.15 C10.2
  Top Layer w20: P15.1 1131.89,-1419.29 U7.5
V_BATT: C6.2 P7.1 P13.VBat P14.1 U3.3 | length 4640.5
  Top Layer w8: P7.1 137.8,-1475.75 137.8,-865.16 399.61,-865.16 412.05,-852.72 412.05,-800.95 388.62,-777.52 373.98,-777.52 129.92,-533.46 129.92,104.33 153.54,127.95 289.37,127.95 ; 290.94,127.95 472.05,-53.15 P13.VBat
  Top Layer w10: 282.48,-1529.88 C6.2@282.48,-1483.19
  Top Layer w20: P7.1 282.48,-1529.88 458.03,-1529.88 ; P13.VBat@470.47,-115.94 P13.VBat ; U3.3 492.76,-1383.5 458.03,-1383.5 458.03,-1529.88 ; P14.1 1868.43,-1537.08 1819.88,-1585.63 513.78,-1585.63 458.03,-1529.88
VA: C3.1 C16.1 U2.5 U6.5 | length 303.4
  Top Layer w8: C16.1@2554.7,-803.17 U6.5
  Top Layer w12: C16.1 2544.25,-909.41 2577.76,-942.91 C3.1 ; U2.5 C3.1@2575.79,-1003.94
VCC: C19.2 C22.1 C29.1 C30.1 C34.1 P100.4 R1.1 R6.1 R7.2 U8.1 U8.8 U8.13 U8.22 U9.3 U10.2 U12.5 | length 2369.3
  Top Layer w8: v1@428.15,-665.35 436.52,-673.72 U8.22 ; U8.1 514.2,-769.12 680.68,-769.12 682.09,-767.72 C30.1 656.01,-689.47 U8.8 ; U8.13 592.94,-579.16 577.76,-563.98 C29.1 615.16,-539.37 631.89,-522.64 v1(631.89,-499.02) ; v1@831.69,-742.13 R6.1 ; v1@1046.26,-842.52 R1.1 ; C34.1@1637.2,-121.65 U9.3 1873.43,-105.71 1847.44,-79.72 1847.44,-49.21 1882.87,-13.78 1914.37,-13.78 2019.68,-119.09 U10.2 C19.2@2063.98,-41.34 ; 2193.9,-1437.01 2194.39,-1437.5 ; C22.1 2259.84,-1421.26 U12.5
  Top Layer w12: P100.4 1832.01,-1166.66 1994.09,-1328.74 2212.6,-1328.74 U12.5 ; v1(2169.29,-1475.39) 2169.29,-1462.6 2194.39,-1437.5 ; 2193.9,-1437.01 C22.1
  other v1: 1045.28,-833.66 683.07,-766.73 829.72,-744.09 424.21,-666.34
VDDD: C2.1 C13.1 U1.2 U6.30 | length 281.4
  Top Layer w8: U1.2 2398.17,-858.27 2344.26,-804.36 C13.1 2344.26,-707.9 2359.03,-693.14 U6.30
VDDIO: C11.1 C17.1 U5.5 U6.20 | length 330.8
  Top Layer w8: C11.1@2422.24,-365.16 C11.1 U5.5 2496.06,-447.83 2556.1,-507.87 ; U6.20 2554.7,-509.28 2556.1,-507.87 ; C17.1 2556.1,-507.87
VH: C8.1 P9.1 P10.1 P16.1 U4.5 | length 1567
  Top Layer w8: P10.1@2740.16,-998.3 P10.1
  Top Layer w12: P10.1 2812.01,-926.45 2812.01,-694.01 2801.61,-683.62 ; P9.1 2801.61,-683.62 ; P16.1@2960.63,128.94 2834.65,128.94 2814.96,109.25 2814.96,-670.28 2801.61,-683.62
  Top Layer w15: U4.5 P10.1@2740.16,-998.3
VHF: P13.8 Q1.1 | length 3275.3
  Top Layer w8: v1(2588.58,-1423.23) 2588.58,-1492.13 Q1.1
  Bottom Layer w8: P13.8 519.49,-370.08 987.2,-370.08 1012.05,-394.92 1012.05,-434.09 1012.05,-534.09 968.62,-577.52 955.48,-577.52 932.05,-600.95 932.05,-734.09 955.48,-757.52 1071.82,-757.52 1133.72,-819.42 1133.72,-839.38 1102.5,-870.6 1102.5,-889.24 1115.68,-902.42 1134.32,-902.42 1137.69,-899.05 2062.44,-899.05 2471.59,-1308.21 2572.31,-1308.21 2585.49,-1321.39 2585.49,-1422.11 v1@2590.55,-1427.17
VHF_GND: P6.1 Q1.3 | length 80.7
  Top Layer w8: Q1.3 P6.1@2743.11,-1511.81
VIN: C7.1 C20.1 C23.1 C25.1 C26.1 C27.1 P3.2 P4.1 P6.2 P13.Vin P14.2 R9.2 U1.3 U2.1 U2.3 U4.1 U5.1 U5.3 U7.1 U12.1 U12.3 | length 7390.8
  Top Layer w8: P3.2@207.8,-128.08 167.32,-87.6 168.27,-86.65 168.27,77.6 191.43,100.75 224.17,100.75 422.24,-97.32 422.24,-139.76 449.8,-167.32 491.14,-167.32 523.62,-134.84 523.62,26.57 600.39,103.35 R9.2@638.78,103.35 ; P13.Vin 973.43,-1418.9 C20.1 ; C20.1@986.22,-1467.52 U7.1 ; 2305.12,-1573.82 U12.1 ; U12.3 2382.87,-1518.7 2382.87,-1573.82
  Top Layer w10: 2188.98,-1570.87 C23.1 ; C7.1@2436.02,-991.14 U1.3 ; C7.1 2409.45,-994.09 2384.84,-1018.7 v2(2379.92,-1018.7) v2@2379.92,-1024.61 ; U2.1@2476.38,-1068.9 C25.1 v2@2379.92,-1024.61 ; U2.3 2466.54,-1138.78 2439.96,-1165.35 2396.65,-1165.35 2379.92,-1148.62 v2@2379.92,-1024.61 ; v2(2513.78,-1217.52) U4.1 ; U5.3 2673.23,-290.35 2689.96,-307.09 2689.96,-375.98 2685.04,-380.91 C27.1
  Top Layer w20: P3.2 P3.2@207.8,-128.08 ; R9.2@638.78,103.35 R9.2 ; v2(1343.5,-1534.45) 1489.57,-1388.38 P14.2 1668.43,-1329.6 1707.68,-1290.35 1882.87,-1290.35 1942.91,-1350.39 1942.91,-1491.14 2025.59,-1573.82 2305.12,-1573.82 2382.87,-1573.82 2455.71,-1573.82 v2@2498.03,-1531.5 ; v2(2495.08,-1527.56) 2501.97,-1527.56 2552.17,-1577.76 2790.35,-1577.76 2805.12,-1562.99 2805.12,-1473.82 P6.2 ; U5.1 2618.11,-365.16 2633.86,-380.91 ; v2(2601.38,-447.83) U5.1@2601.38,-375.98
  Bottom Layer w20: 106.3,-708.66 108.27,-706.69 ; P3.2 108.27,-238.31 108.27,-706.69 ; v2(1343.5,-1534.45) 1088.98,-1534.45 P13.Vin 972.05,-1470.87 849.41,-1593.5 124.02,-1593.5 108.27,-1577.76 108.27,-706.69
  Bottom Layer w30: P4.1 106.3,-708.66
VSENS: P13.A14 R9.1 R10.2 | length 435.5
  Top Layer w8: R9.1 641.73,37.4 R10.2 704.72,-1.97 723.43,-20.67 723.43,-141.73 754.33,-172.64 816.93,-172.64 P13.A14
pads on no net: P2. P2.4 P13.3.3V P13.3.3V2 P13.A11 P13.AGND P13.AREF P13.GND2 P100.0 P100.1 P100.8 U6.2 U6.4 U6.6 U6.8 U6.9 U6.11 U6.12 U6.16 U6.17 U6.18 U6.19 U6.22 U6.28 U8.2 U8.3 U8.4 U8.5 U8.6 U8.7 U8.12 U8.14 U8.15 U8.16 U8.17 U8.19 U8.21 U9.1 U11.2 U11.5
copper on no net: | length 208.7
  Top Layer w20: 2139.76,69.88 2348.43,69.88

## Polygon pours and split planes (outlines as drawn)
AGND on Internal Plane 1 (split plane): 2813.56,-1592.1 2269.59,-1591.9 2264.82,168.68 2813.56,168.68
DGND on Internal Plane 1 (split plane): 2199.67,-1591.88 123.03,-1591.14 123.03,-40.14 120.08,-37.19 106.71,-37.19 106.71,168.68 2201.75,168.68
VIN on Internal Plane 2 (split plane): 2813.56,-1592.1 2269.6,-1591.9 2265.79,168.68 2813.56,168.68
VCC on Internal Plane 2 (split plane): 2199.68,-1591.88 123.03,-1591.14 123.03,-37.19 106.71,-37.19 106.71,168.68 2202.72,168.68

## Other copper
Internal Plane 1 (plane layer: these items are gaps in the copper):
  pour cut-out: 2264.76,188.98 2201.77,188.78 2199.65,-1612.2 2269.65,-1612.2
  pour cut-out: 30.51,-37.19 120.08,-37.19 123.03,-40.14 123.03,-1617.22 32.39,-1617.22 30.51,-1619.09
Internal Plane 2 (plane layer: these items are gaps in the copper):
  pour cut-out: 2265.75,188.78 2202.76,188.78 2199.65,-1612.2 2269.65,-1612.2
  pour cut-out: 30.51,-37.19 123.03,-37.19 123.03,-1618.11 122.05,-1619.09 30.51,-1619.09

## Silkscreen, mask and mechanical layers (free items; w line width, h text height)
Top Overlay:
  circle w10: c1755.91,-1021.65 r450
  circle w10: c1758.86,-1015.75 r579
  circle w10: c2501.87,-20.33 r20
  lines w10: 62.01,-1572.83 62.01,150.59 ; 1598.43,-319.88 1598.43,158.15 ; 2421.87,-20.33 2501.87,-20.33 ; 2501.87,-16.75 2501.87,68.25
  text "-" at 3225.39,118.11 h60
  text "+" at 2896.65,113.19 h60 r90
  text "X" at 2488.19,62.01 h80 r90
  text "SDA" at 268.7,41.34 h60
  text "Y" at 2385.83,-39.37 h80 r90
  text "v3.0" at 2688.98,-54.13 h60 r90
  text "SCL" at 264.76,-57.09 h60
  text "Z" at 2572.84,-102.36 h80 r90
  text "12" at 294.29,-117.13 h50
  text "13" at 1016.73,-128.94 h50
  text "V" at 114.17,-163.39 h60
  text "14" at 1009.84,-209.65 h50
  text "11" at 298.23,-231.3 h50
  text "AMX" at 2691.93,-260.83 h100 r90
  text "G" at 115.16,-268.7 h60
  text "10" at 293.31,-303.15 h50
  text "15" at 1012.8,-306.1 h50
  text "Loggerhead" at 2801.18,-405.51 h120 r90
  text "9" at 313.98,-406.5 h50
  text "16" at 1010.83,-421.26 h50
  text "+" at -58.07,-479.33 h160 r180
  text "-" at -471.46,-488.19 h160 r180
  text "-" at 2826.77,-488.19 h60 r90
  text "17" at 1009.84,-502.95 h50
  text "8" at 313.98,-503.94 h50
  text "18" at 997.05,-597.44 h50
  text "7" at 313.98,-605.31 h50
  text "+" at 2831.69,-696.85 h60 r90
  text "6" at 313.98,-709.65 h50
  text "STOP" at 1494.09,-725.39 h70 r30
  text "19" at 906.5,-771.65 h50
  text "-" at 2828.74,-789.37 h60 r90
  text "5" at 313.98,-812.01 h50
  text "20" at 892.72,-856.3 h50
  text "A11" at 767.72,-890.75 h50
  text "4" at 315.94,-908.46 h50
  text "4" at 99.41,-947.83 h50
  text "21" at 901.57,-965.55 h50
  text "15" at 1127.95,-976.38 h50
  text "A10" at 768.7,-987.2 h50
  text "+" at 2830.71,-992.13 h60 r90
  text "3" at 316.93,-1005.91 h50
  text "2" at 101.38,-1050.2 h50
  text "22" at 897.64,-1065.94 h50
  text "Tx" at 1126.97,-1078.74 h50
  text "2" at 329.72,-1088.58 h50
  text "G" at 94.49,-1153.54 h60
  text "23" at 900.59,-1166.34 h50
  text "Rx" at 1131.89,-1178.15 h50
  text "1" at 313.98,-1205.71 h50
  text "PGM" at 2159.45,-1221.46 h60 r90
  text "CHARGE" at 636.81,-1246.06 h60
  text "SS" at 93.5,-1260.83 h50
  text "G" at 1137.8,-1271.65 h50
  text "0" at 313.98,-1309.05 h50
  text "SR" at 95.47,-1361.22 h50
  text "OFF" at 1906.5,-1376.97 h70
  text "3.6V" at 1135.83,-1393.7 h50
  text "ON" at 1531.5,-1393.7 h70
  text "G" at 313.98,-1408.46 h50
  text "V" at 2820.87,-1431.1 h60 r90
  text "-" at 92.52,-1432.09 h120 r270
  text "VHF" at 2675.2,-1460.63 h60 r90
  text "Vin" at 887.8,-1471.46 h50
  text "+" at 137.8,-1498.03 h100 r180
  text "G" at 2823.82,-1533.46 h60 r90
  text "D-" at 820.87,-1556.1 h60 r90
  text "D+" at 594.49,-1557.09 h60 r90
  text "BAT" at 251.97,-1586.61 h60
Bottom Overlay:
  text "-" at 3244.84,139.37 h60 r180
  text "+" at 2896.65,113.19 h60 r90
  text "-" at 2684.06,-470.47 h140 r90
  text "L" at 2668.31,-566.93 h100 r90
  text "+" at 2684.06,-722.44 h140
  text "-" at 2717.52,-797.24 h140 r90
  text "R" at 2717.52,-857.28 h100 r90
  text "+" at 2652.56,-1025.59 h140
Mechanical 1:
  lines w10: 3249.21,188.78 2833.66,188.78 86.61,188.78 -99.41,2.76 -99.41,-329.72 -100.39,-330.71 -259.84,-475.39 -577.56,-475.39 -647.64,-545.47 -647.64,-876.97 -584.65,-939.96 -259.84,-939.96 -99.41,-1100.39 -99.41,-1426.18 86.61,-1612.2 2833.66,-1612.2 2833.66,26.57 2875.98,68.9 3256.89,68.9 3270.67,82.68 3270.67,167.32 3250,187.99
